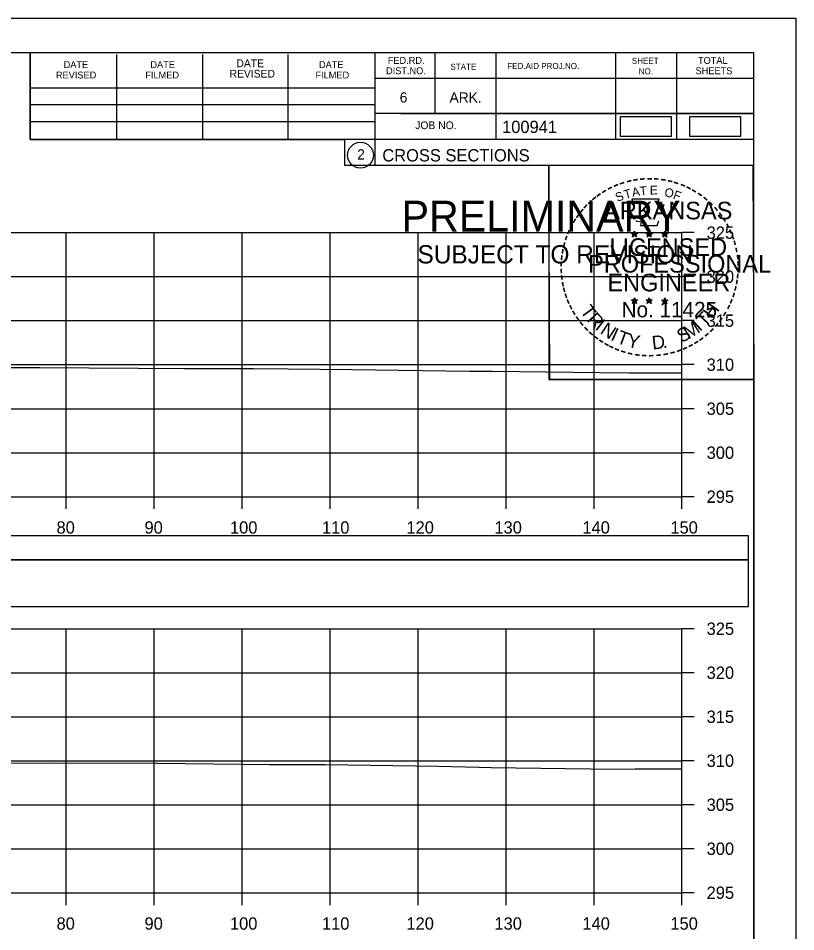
# Model space of a CAD drawing. Extents: x 1370538 to 1372872, y 376220 to 381127.
# Drawn here: x 1371449.9 to 1371538.2, y 380794.6 to 380898.4 of the extents above; entities that cross this region are included whole.
import ezdxf

# ---------------------------------------------------------------- set-up
doc = ezdxf.new("R2010")
doc.units = 0
for name, color, linetype in [('Default', 7, 'Continuous'), ('R_Border Notes', 7, 'Continuous'), ('R_Border PE', 7, 'Continuous'), ('R_Border Prem', 7, 'Continuous'), ('R_Dimension', 7, 'Continuous'), ('R_Grid', 7, 'Continuous'), ('R_No Plot', 7, 'Continuous'), ('T_Detection Zones', 7, 'Continuous'), ('T_Indications', 7, 'Continuous'), ('T_Notes', 7, 'Continuous')]:
    doc.layers.add(name, color=color, linetype=linetype)

msp = doc.modelspace()

# ---------------------------------------------------------------- linework, layer by layer
at = {"layer": 'Default'}
for points in [[(1371518.28, 380885), (1371524.11, 380885), (1371524.11, 380887.19), (1371518.28, 380887.19)], [(1371526.15, 380885), (1371531.98, 380885), (1371531.98, 380887.19), (1371526.15, 380887.19)]]:
    msp.add_lwpolyline(points, close=True, dxfattribs=at)
at = {"layer": 'R_Border Notes'}
for p, q in [((1371217.29, 380894.5), (1371533.47, 380894.5)), ((1371451.21, 380884.62), (1371451.21, 380894.5)), ((1371461.07, 380884.62), (1371461.07, 380894.3)), ((1371470.83, 380884.62), (1371470.83, 380894.3)), ((1371480.51, 380884.62), (1371480.51, 380894.3)), ((1371490.37, 380894.5), (1371490.37, 380881.7)), ((1371497.21, 380894.5), (1371497.21, 380887.56)), ((1371504.15, 380894.5), (1371504.15, 380884.62)), ((1371517.73, 380894.5), (1371517.73, 380884.62)), ((1371524.67, 380894.5), (1371524.67, 380884.62)), ((1371533.47, 380689.04), (1371533.47, 380894.5)), ((1371533.47, 380891.56), (1371490.37, 380891.56)), ((1371533.47, 380891.58), (1371533.47, 380891.58)), ((1371451.21, 380890.48), (1371490.37, 380890.48)), ((1371451.21, 380888.62), (1371490.37, 380888.62)), ((1371533.47, 380887.56), (1371490.37, 380887.56)), ((1371493.33, 380887.56), (1371533.47, 380887.56)), ((1371451.21, 380884.62), (1371451.21, 380886.68)), ((1371451.21, 380886.68), (1371490.37, 380886.68)), ((1371533.47, 380884.62), (1371451.21, 380884.62)), ((1371490.37, 380881.7), (1371533.47, 380881.7))]:
    msp.add_line(p, q, dxfattribs=at)
msp.add_circle((1371488.75, 380882.84), 1.47, dxfattribs=at)
at = {"layer": 'R_Border Prem'}
for p, q in [((1371525.29, 380844.04), (1371525.29, 380874.04)), ((1371526.69, 380874.04), (1371525.29, 380874.04)), ((1371526.69, 380869.04), (1371525.29, 380869.04)), ((1371526.69, 380864.04), (1371525.29, 380864.04)), ((1371526.69, 380859.04), (1371525.29, 380859.04)), ((1371526.69, 380854.04), (1371525.29, 380854.04)), ((1371526.69, 380849.04), (1371525.29, 380849.04)), ((1371225.29, 380844.04), (1371525.29, 380844.04)), ((1371455.29, 380842.64), (1371455.29, 380844.04)), ((1371465.29, 380842.64), (1371465.29, 380844.04)), ((1371475.29, 380842.64), (1371475.29, 380844.04)), ((1371485.29, 380842.64), (1371485.29, 380844.04)), ((1371495.29, 380842.64), (1371495.29, 380844.04)), ((1371505.29, 380842.64), (1371505.29, 380844.04)), ((1371515.29, 380842.64), (1371515.29, 380844.04)), ((1371525.29, 380842.64), (1371525.29, 380844.04)), ((1371526.69, 380844.04), (1371525.29, 380844.04)), ((1371525.29, 380799.04), (1371525.29, 380829.04)), ((1371526.69, 380829.04), (1371525.29, 380829.04)), ((1371526.69, 380824.04), (1371525.29, 380824.04)), ((1371526.69, 380819.04), (1371525.29, 380819.04)), ((1371526.69, 380814.04), (1371525.29, 380814.04)), ((1371526.69, 380809.04), (1371525.29, 380809.04)), ((1371526.69, 380804.04), (1371525.29, 380804.04)), ((1371225.29, 380799.04), (1371525.29, 380799.04)), ((1371455.29, 380797.64), (1371455.29, 380799.04)), ((1371465.29, 380797.64), (1371465.29, 380799.04)), ((1371475.29, 380797.64), (1371475.29, 380799.04)), ((1371485.29, 380797.64), (1371485.29, 380799.04)), ((1371495.29, 380797.64), (1371495.29, 380799.04)), ((1371505.29, 380797.64), (1371505.29, 380799.04)), ((1371515.29, 380797.64), (1371515.29, 380799.04)), ((1371525.29, 380797.64), (1371525.29, 380799.04)), ((1371526.69, 380799.04), (1371525.29, 380799.04))]:
    msp.add_line(p, q, dxfattribs=at)
at = {"layer": 'R_Dimension'}
for points in [[(1371401.53, 380858.5), (1371411.24, 380858.63), (1371422.37, 380858.75), (1371423.05, 380858.75), (1371427.22, 380858.76), (1371442.19, 380858.7), (1371448.25, 380858.71), (1371452.25, 380858.7), (1371463.47, 380858.64), (1371468.75, 380858.6), (1371476.59, 380858.6), (1371480.51, 380858.56), (1371487.78, 380858.49), (1371501.13, 380858.31), (1371503.75, 380858.29), (1371515.95, 380858.14), (1371519.26, 380858.1), (1371525.29, 380858.11)], [(1371402.33, 380813.37), (1371403.69, 380813.56), (1371411.36, 380813.67), (1371417.41, 380813.73), (1371422.22, 380813.78), (1371424.91, 380813.79), (1371434.55, 380813.75), (1371453.42, 380813.78), (1371465.6, 380813.75), (1371465.66, 380813.75), (1371478.42, 380813.62), (1371484.75, 380813.6), (1371497.59, 380813.41), (1371502.24, 380813.31), (1371503.61, 380813.28), (1371517.7, 380813.09), (1371519.96, 380813.11), (1371520.68, 380813.12), (1371525.29, 380813.12)]]:
    msp.add_lwpolyline(points, dxfattribs=at)
at = {"layer": 'R_Grid'}
for p, q in [((1371225.29, 380874.04), (1371525.29, 380874.04)), ((1371455.29, 380844.04), (1371455.29, 380874.04)), ((1371465.29, 380844.04), (1371465.29, 380874.04)), ((1371475.29, 380844.04), (1371475.29, 380874.04)), ((1371485.29, 380844.04), (1371485.29, 380874.04)), ((1371495.29, 380844.04), (1371495.29, 380874.04)), ((1371505.29, 380844.04), (1371505.29, 380874.04)), ((1371515.29, 380844.04), (1371515.29, 380874.04)), ((1371525.29, 380844.04), (1371525.29, 380874.04)), ((1371225.29, 380869.04), (1371525.29, 380869.04)), ((1371225.29, 380864.04), (1371525.29, 380864.04)), ((1371225.29, 380859.04), (1371525.29, 380859.04)), ((1371225.29, 380854.04), (1371525.29, 380854.04)), ((1371225.29, 380849.04), (1371525.29, 380849.04)), ((1371225.29, 380844.04), (1371525.29, 380844.04)), ((1371225.29, 380829.04), (1371525.29, 380829.04)), ((1371455.29, 380799.04), (1371455.29, 380829.04)), ((1371465.29, 380799.04), (1371465.29, 380829.04)), ((1371475.29, 380799.04), (1371475.29, 380829.04)), ((1371485.29, 380799.04), (1371485.29, 380829.04)), ((1371495.29, 380799.04), (1371495.29, 380829.04)), ((1371505.29, 380799.04), (1371505.29, 380829.04)), ((1371515.29, 380799.04), (1371515.29, 380829.04)), ((1371525.29, 380799.04), (1371525.29, 380829.04)), ((1371225.29, 380824.04), (1371525.29, 380824.04)), ((1371225.29, 380819.04), (1371525.29, 380819.04)), ((1371225.29, 380814.04), (1371525.29, 380814.04)), ((1371225.29, 380809.04), (1371525.29, 380809.04)), ((1371225.29, 380804.04), (1371525.29, 380804.04)), ((1371225.29, 380799.04), (1371525.29, 380799.04))]:
    msp.add_line(p, q, dxfattribs=at)
at = {"layer": 'R_No Plot'}
for p, q in [((1371204.89, 380898.4), (1371538.22, 380898.4)), ((1371509.5, 380859.25), (1371509.5, 380859.25))]:
    msp.add_line(p, q, dxfattribs=at)
for points in [[(1371204.88, 380898.4), (1371538.22, 380898.4), (1371538.22, 380685.06), (1371204.88, 380685.06)], [(1371451.21, 380894.5), (1371451.21, 380884.62), (1371486.94, 380884.62), (1371486.94, 380881.7), (1371510.14, 380881.7), (1371510.14, 380857.37), (1371533.47, 380857.37), (1371533.47, 380689.04), (1371217.29, 380689.04), (1371217.29, 380894.5)], [(1371510.14, 380881.7), (1371533.35, 380881.7), (1371533.47, 380857.37), (1371510.26, 380857.37)]]:
    msp.add_lwpolyline(points, close=True, dxfattribs=at)
at = {"layer": 'T_Detection Zones'}
for points in [[(1371217.73, 380836.87), (1371532.86, 380836.87), (1371532.86, 380839.58), (1371217.73, 380839.58)], [(1371217.73, 380831.55), (1371532.86, 380831.55), (1371532.86, 380836.87), (1371217.73, 380836.87)]]:
    msp.add_lwpolyline(points, close=True, dxfattribs=at)
at = {"layer": 'T_Indications'}
for p, q in [((1371519.55, 380873.96), (1371519.9, 380873.85)), ((1371519.55, 380873.96), (1371519.8, 380873.91)), ((1371519.55, 380873.96), (1371519.79, 380873.84)), ((1371519.68, 380873.55), (1371519.9, 380873.85)), ((1371519.68, 380873.55), (1371519.81, 380873.8)), ((1371519.68, 380873.55), (1371519.9, 380873.77)), ((1371519.9, 380874.21), (1371519.86, 380873.96)), ((1371519.9, 380873.85), (1371519.9, 380874.21)), ((1371519.9, 380874.21), (1371519.95, 380873.96)), ((1371520.25, 380873.96), (1371519.9, 380873.85)), ((1371520.11, 380873.55), (1371519.9, 380873.85)), ((1371520.11, 380873.55), (1371519.9, 380873.77)), ((1371520.25, 380873.96), (1371519.96, 380873.91)), ((1371520.11, 380873.55), (1371519.98, 380873.84)), ((1371520.25, 380873.96), (1371520.04, 380873.86)), ((1371521.22, 380873.96), (1371521.57, 380873.85)), ((1371521.22, 380873.96), (1371521.47, 380873.91)), ((1371521.22, 380873.96), (1371521.46, 380873.84)), ((1371521.35, 380873.55), (1371521.57, 380873.85)), ((1371521.35, 380873.55), (1371521.48, 380873.8)), ((1371521.35, 380873.55), (1371521.57, 380873.77)), ((1371521.57, 380874.21), (1371521.53, 380873.96)), ((1371521.57, 380873.85), (1371521.57, 380874.21)), ((1371521.57, 380874.21), (1371521.62, 380873.96)), ((1371521.92, 380873.96), (1371521.57, 380873.85)), ((1371521.78, 380873.55), (1371521.57, 380873.85)), ((1371521.78, 380873.55), (1371521.57, 380873.77)), ((1371521.92, 380873.96), (1371521.63, 380873.91)), ((1371521.78, 380873.55), (1371521.65, 380873.84)), ((1371521.92, 380873.96), (1371521.71, 380873.86)), ((1371522.99, 380873.95), (1371523.33, 380873.84)), ((1371522.99, 380873.95), (1371523.24, 380873.9)), ((1371522.99, 380873.95), (1371523.22, 380873.83)), ((1371523.12, 380873.54), (1371523.33, 380873.84)), ((1371523.12, 380873.54), (1371523.24, 380873.78)), ((1371523.12, 380873.54), (1371523.33, 380873.76)), ((1371523.33, 380874.2), (1371523.29, 380873.95)), ((1371523.33, 380873.84), (1371523.33, 380874.2)), ((1371523.33, 380874.2), (1371523.38, 380873.95)), ((1371523.68, 380873.95), (1371523.33, 380873.84)), ((1371523.55, 380873.54), (1371523.33, 380873.84)), ((1371523.55, 380873.54), (1371523.33, 380873.75)), ((1371523.68, 380873.95), (1371523.4, 380873.9)), ((1371523.55, 380873.54), (1371523.41, 380873.83)), ((1371523.68, 380873.95), (1371523.48, 380873.85)), ((1371519.55, 380866.39), (1371519.9, 380866.28)), ((1371519.55, 380866.39), (1371519.8, 380866.34)), ((1371519.55, 380866.39), (1371519.78, 380866.26)), ((1371519.68, 380865.98), (1371519.9, 380866.28)), ((1371519.9, 380866.64), (1371519.86, 380866.39)), ((1371519.9, 380866.28), (1371519.9, 380866.64)), ((1371519.9, 380866.64), (1371519.95, 380866.39)), ((1371520.24, 380866.39), (1371519.9, 380866.28)), ((1371520.11, 380865.98), (1371519.9, 380866.28)), ((1371520.24, 380866.39), (1371519.96, 380866.34)), ((1371520.11, 380865.98), (1371519.97, 380866.27)), ((1371520.24, 380866.39), (1371520.04, 380866.28)), ((1371521.22, 380866.39), (1371521.57, 380866.28)), ((1371521.22, 380866.39), (1371521.47, 380866.34)), ((1371521.22, 380866.39), (1371521.45, 380866.26)), ((1371521.35, 380865.98), (1371521.57, 380866.28)), ((1371521.57, 380866.64), (1371521.52, 380866.39)), ((1371521.57, 380866.28), (1371521.57, 380866.64)), ((1371521.57, 380866.64), (1371521.61, 380866.39)), ((1371521.91, 380866.39), (1371521.57, 380866.28)), ((1371521.78, 380865.98), (1371521.57, 380866.28)), ((1371521.91, 380866.39), (1371521.63, 380866.34)), ((1371521.78, 380865.98), (1371521.64, 380866.27)), ((1371521.91, 380866.39), (1371521.71, 380866.28)), ((1371522.98, 380866.38), (1371523.33, 380866.27)), ((1371522.98, 380866.38), (1371523.24, 380866.33)), ((1371522.98, 380866.38), (1371523.22, 380866.25)), ((1371523.33, 380866.63), (1371523.29, 380866.38)), ((1371523.33, 380866.27), (1371523.33, 380866.63)), ((1371523.33, 380866.63), (1371523.38, 380866.38)), ((1371523.68, 380866.38), (1371523.33, 380866.27)), ((1371523.68, 380866.38), (1371523.39, 380866.33)), ((1371523.68, 380866.38), (1371523.48, 380866.27)), ((1371519.68, 380865.98), (1371519.81, 380866.22)), ((1371519.68, 380865.98), (1371519.89, 380866.2)), ((1371520.11, 380865.98), (1371519.89, 380866.19)), ((1371521.35, 380865.98), (1371521.48, 380866.22)), ((1371521.35, 380865.98), (1371521.56, 380866.2)), ((1371521.78, 380865.98), (1371521.56, 380866.19)), ((1371523.12, 380865.97), (1371523.33, 380866.27)), ((1371523.12, 380865.97), (1371523.24, 380866.21)), ((1371523.12, 380865.97), (1371523.33, 380866.19)), ((1371523.55, 380865.97), (1371523.33, 380866.27)), ((1371523.55, 380865.97), (1371523.33, 380866.18)), ((1371523.55, 380865.97), (1371523.41, 380866.26))]:
    msp.add_line(p, q, dxfattribs=at)
for points in [[(1371519.59, 380877.84), (1371519.86, 380877.01)], [(1371523.1, 380876.92), (1371523.25, 380877.2), (1371522.56, 380877.18), (1371522.71, 380877.84), (1371519.59, 380877.84)], [(1371520.08, 380875.41), (1371520.08, 380875.33), (1371520.65, 380875.31), (1371520.59, 380874.84), (1371522.46, 380874.84), (1371522.66, 380875.37)], [(1371519.9, 380874.21), (1371520.11, 380873.55), (1371519.55, 380873.96), (1371520.25, 380873.96), (1371519.68, 380873.55), (1371519.9, 380874.21)], [(1371521.57, 380874.21), (1371521.78, 380873.55), (1371521.22, 380873.96), (1371521.92, 380873.96), (1371521.35, 380873.55), (1371521.57, 380874.21)], [(1371523.33, 380874.2), (1371523.55, 380873.54), (1371522.99, 380873.95), (1371523.68, 380873.95), (1371523.12, 380873.54), (1371523.33, 380874.2)], [(1371519.9, 380866.64), (1371520.11, 380865.98), (1371519.55, 380866.39), (1371520.24, 380866.39), (1371519.68, 380865.98), (1371519.9, 380866.64)], [(1371521.57, 380866.64), (1371521.78, 380865.98), (1371521.22, 380866.39), (1371521.91, 380866.39), (1371521.35, 380865.98), (1371521.57, 380866.64)], [(1371523.33, 380866.63), (1371523.55, 380865.97), (1371522.98, 380866.38), (1371523.68, 380866.38), (1371523.12, 380865.97), (1371523.33, 380866.63)]]:
    msp.add_lwpolyline(points, dxfattribs=at)
for centre, radius in [((1371519.9, 380873.85), 0.172), ((1371519.9, 380873.85), 0.145), ((1371519.9, 380873.85), 0.116), ((1371519.9, 380873.85), 0.0991), ((1371519.9, 380873.85), 0.0747), ((1371519.9, 380873.85), 0.0495), ((1371519.9, 380873.85), 0.0296), ((1371521.57, 380873.85), 0.172), ((1371521.57, 380873.85), 0.145), ((1371521.57, 380873.85), 0.116), ((1371521.57, 380873.85), 0.0991), ((1371521.57, 380873.85), 0.0747), ((1371521.57, 380873.85), 0.0495), ((1371521.57, 380873.85), 0.0296), ((1371523.33, 380873.84), 0.172), ((1371523.33, 380873.84), 0.145), ((1371523.33, 380873.84), 0.116), ((1371523.33, 380873.84), 0.0991), ((1371523.33, 380873.84), 0.0747), ((1371523.33, 380873.84), 0.0495), ((1371523.33, 380873.84), 0.0296), ((1371519.9, 380866.27), 0.172), ((1371519.9, 380866.27), 0.145), ((1371519.9, 380866.27), 0.116), ((1371519.9, 380866.27), 0.0991), ((1371519.9, 380866.27), 0.0747), ((1371519.9, 380866.27), 0.0495), ((1371519.9, 380866.27), 0.0296), ((1371521.56, 380866.27), 0.172), ((1371521.56, 380866.27), 0.145), ((1371521.56, 380866.27), 0.116), ((1371521.56, 380866.27), 0.0991), ((1371521.56, 380866.27), 0.0747), ((1371521.56, 380866.27), 0.0495), ((1371521.56, 380866.27), 0.0296), ((1371523.33, 380866.26), 0.172), ((1371523.33, 380866.26), 0.145), ((1371523.33, 380866.26), 0.116), ((1371523.33, 380866.26), 0.0991), ((1371523.33, 380866.26), 0.0747), ((1371523.33, 380866.26), 0.0495), ((1371523.33, 380866.26), 0.0296)]:
    msp.add_circle(centre, radius, dxfattribs=at)

# ---------------------------------------------------------------- texts
at = {"layer": 'R_Border Notes'}
for s, height, p in [('DATE', 0.782, (1371455.01, 380892.74)), ('DATE', 0.782, (1371464.87, 380892.74)), ('DATE', 0.879, (1371474.65, 380892.84)), ('DATE', 0.782, (1371484.03, 380892.74)), ('FED.RD.', 0.782, (1371491.85, 380893.22)), ('FED.AID PROJ.NO.', 0.684, (1371505.43, 380892.64)), ('SHEET', 0.684, (1371519.59, 380893.22)), ('TOTAL', 0.782, (1371527.11, 380893.22)), ('REVISED', 0.782, (1371454.13, 380891.56)), ('FILMED', 0.782, (1371464.29, 380891.56)), ('REVISED', 0.879, (1371473.87, 380891.66)), ('FILMED', 0.782, (1371483.63, 380891.56)), ('DIST.NO.', 0.782, (1371491.65, 380892.04)), ('STATE', 0.684, (1371498.97, 380892.54)), ('NO.', 0.684, (1371520.37, 380892.04)), ('SHEETS', 0.782, (1371526.83, 380892.04)), ('6', 1.17, (1371493.21, 380888.82)), ('ARK.', 1.172, (1371498.87, 380888.82)), ('JOB NO.', 0.879, (1371494.97, 380885.8)), ('100941', 1.4, (1371504.84, 380885.36)), ('2', 1.17, (1371488.37, 380882.35)), ('CROSS SECTIONS', 1.4, (1371491.23, 380882.13))]:
    msp.add_text(s, height=height, rotation=360, dxfattribs=at).set_placement(p)
at = {"layer": 'R_Border PE'}
for s, p in [('325', (1371528.09, 380873.34)), ('320', (1371528.09, 380868.34)), ('315', (1371528.09, 380863.34)), ('310', (1371528.09, 380858.34)), ('305', (1371528.09, 380853.34)), ('300', (1371528.09, 380848.34)), ('295', (1371528.09, 380843.34)), ('80', (1371454.2, 380839.84)), ('90', (1371464.2, 380839.84)), ('100', (1371473.91, 380839.84)), ('110', (1371484.37, 380839.84)), ('120', (1371493.97, 380839.84)), ('130', (1371503.97, 380839.84)), ('140', (1371513.97, 380839.84)), ('150', (1371523.97, 380839.84)), ('325', (1371528.09, 380828.34)), ('320', (1371528.09, 380823.34)), ('315', (1371528.09, 380818.34)), ('310', (1371528.09, 380813.34)), ('305', (1371528.09, 380808.34)), ('300', (1371528.09, 380803.34)), ('295', (1371528.09, 380798.34)), ('80', (1371454.2, 380794.84)), ('90', (1371464.2, 380794.84)), ('100', (1371473.91, 380794.84)), ('110', (1371484.37, 380794.84)), ('120', (1371493.97, 380794.84)), ('130', (1371503.97, 380794.84)), ('140', (1371513.97, 380794.84)), ('150', (1371523.97, 380794.84))]:
    msp.add_text(s, height=1.4, dxfattribs=at).set_placement(p)
at = {"layer": 'T_Indications'}
for s, height, rotation, p in [('-', 1.6, 19.1761, (1371518.34, 380878.96)), ('-', 1.6, 13.6301, (1371519.09, 380879.21)), ('-', 1.6, 10.2193, (1371519.77, 380879.37)), ('-', 1.6, 5.8968, (1371520.5, 380879.48)), ('-', 1.6, 0.1862, (1371521.27, 380879.55)), ('-', 1.6, 357.743, (1371521.99, 380879.54)), ('-', 1.6, 352.1617, (1371522.74, 380879.48)), ('-', 1.6, 347.2049, (1371523.46, 380879.37)), ('-', 1.6, 342.3362, (1371524.09, 380879.21)), ('-', 1.6, 34.0636, (1371516.48, 380878.01)), ('-', 1.6, 28.7918, (1371517.07, 380878.38)), ('-', 1.6, 24.3072, (1371517.71, 380878.7)), ('T', 1, 16.4036, (1371518.86, 380877.85)), ('A', 1, 11.2132, (1371519.69, 380878.1)), ('T', 1, 6.0228, (1371520.54, 380878.26)), ('E', 1, 0.8323, (1371521.64, 380878.37)), ('O', 1, 350.4515, (1371523.25, 380878.16)), ('F', 1, 340.0707, (1371524.2, 380877.94)), ('-', 1.6, 337.8551, (1371524.83, 380878.99)), ('-', 1.6, 334.1211, (1371525.46, 380878.72)), ('-', 1.6, 329.6409, (1371526.04, 380878.43)), ('-', 1.6, 42.9622, (1371514.99, 380876.82)), ('-', 1.6, 38.9507, (1371515.42, 380877.24)), ('-', 1.6, 36.2317, (1371515.9, 380877.61)), ('S', 1, 21.594, (1371517.95, 380877.52)), ('-', 1.6, 325.8627, (1371526.68, 380878.07)), ('-', 1.6, 320.5297, (1371527.29, 380877.65)), ('-', 1.6, 50.6142, (1371514.14, 380875.85)), ('-', 1.6, 48.423, (1371514.54, 380876.34)), ('ARKANSAS', 2, 360, (1371516.45, 380875.55)), ('-', 1.6, 315.5786, (1371527.89, 380877.16)), ('-', 1.6, 309.8797, (1371528.46, 380876.61)), ('-', 1.6, 58.0706, (1371513.4, 380874.76)), ('-', 1.6, 54.2325, (1371513.73, 380875.29)), ('-', 1.6, 306.6522, (1371528.98, 380876.01)), ('-', 1.4, 303.6753, (1371529.47, 380875.44)), ('-', 1.6, 62.8713, (1371513.09, 380874.15)), ('-', 1.6, 299.6684, (1371529.79, 380874.83)), ('-', 1.6, 72.3945, (1371512.61, 380872.91)), ('-', 1.6, 67.7743, (1371512.83, 380873.54)), ('DWB', 0.01, 360, (1371519.89, 380873.84)), ('DWB', 0.01, 360, (1371521.56, 380873.84)), ('DWB', 0.01, 360, (1371523.32, 380873.83)), ('-', 1.6, 294.6628, (1371530.11, 380874.22)), ('-', 1.6, 290.5728, (1371530.37, 380873.64)), ('-', 1.6, 75.461, (1371512.41, 380872.19)), ('LICENSED', 2, 360, (1371517.04, 380871.4)), ('-', 1.6, 285.1233, (1371530.6, 380873.06)), ('-', 1.6, 85.1863, (1371512.2, 380870.79)), ('-', 1.6, 81.2013, (1371512.28, 380871.48)), ('PROFESSIONAL', 2, 360, (1371514.62, 380869.5)), ('-', 1.6, 280.5493, (1371530.8, 380872.32)), ('-', 1.6, 276.5962, (1371530.96, 380871.55)), ('-', 1.6, 89.0622, (1371512.18, 380870.09)), ('-', 1.6, 274.3301, (1371531.02, 380870.83)), ('-', 1.6, 94.1959, (1371512.21, 380869.36)), ('ENGINEER', 2, 360, (1371516.81, 380867.37)), ('-', 1.6, 269.9407, (1371531.06, 380870.2)), ('-', 1.6, 98.9479, (1371512.29, 380868.69)), ('-', 1.6, 101.7149, (1371512.42, 380867.96)), ('-', 1.6, 260.9953, (1371530.97, 380868.88)), ('-', 1.6, 263.5172, (1371531.04, 380869.53)), ('-', 1.6, 105.4578, (1371512.58, 380867.37)), ('-', 1.6, 255.7626, (1371530.86, 380868.2)), ('-', 1.6, 109.0874, (1371512.8, 380866.74)), ('-', 1.6, 114.0643, (1371513.05, 380866.14)), ('DWB', 0.01, 360, (1371519.88, 380866.27)), ('DWB', 0.01, 360, (1371521.55, 380866.27)), ('DWB', 0.01, 360, (1371523.32, 380866.26)), ('-', 1.6, 247.8887, (1371530.45, 380866.81)), ('-', 1.6, 252.8681, (1371530.68, 380867.48)), ('-', 1.6, 115.7289, (1371513.36, 380865.52)), ('T', 1.54, 306.0406, (1371513.66, 380865.11)), ('No. 11425', 1.757, 360, (1371518.43, 380864.42)), ('H', 1.54, 54.6088, (1371528.78, 380864.15)), ('-', 1.6, 244.6197, (1371530.19, 380866.18)), ('-', 1.6, 120.4471, (1371513.71, 380864.94)), ('-', 1.6, 125.8934, (1371514.12, 380864.37)), ('R', 1.54, 314.005, (1371514.42, 380864.07)), ('I', 1.54, 321.9694, (1371515.32, 380863.13)), ('T', 1.54, 46.6444, (1371527.89, 380863.21)), ('-', 1.6, 233.8452, (1371529.4, 380864.77)), ('-', 1.6, 239.0712, (1371529.8, 380865.43)), ('-', 1.6, 130.7181, (1371514.58, 380863.82)), ('-', 1.6, 134.2238, (1371515.1, 380863.28)), ('N', 1.54, 326.5002, (1371515.89, 380862.66)), ('I', 1.54, 335.3603, (1371517.09, 380861.88)), ('S', 1.54, 26.9312, (1371525.2, 380861.48)), ('M', 1.54, 32.6563, (1371526.04, 380861.88)), ('I', 1.54, 42.1136, (1371527.32, 380862.73)), ('-', 1.6, 225.7653, (1371528.49, 380863.64)), ('-', 1.6, 231.2538, (1371528.97, 380864.21)), ('-', 1.6, 138.9338, (1371515.62, 380862.81)), ('-', 1.6, 144.6463, (1371516.18, 380862.41)), ('T', 1.54, 339.8912, (1371517.76, 380861.55)), ('Y', 1.54, 347.8556, (1371518.97, 380861.1)), ('D', 1.54, 6.3969, (1371521.96, 380860.75)), ('-', 1.6, 215.7363, (1371527.42, 380862.66)), ('-', 1.6, 221.0851, (1371527.96, 380863.14)), ('-', 1.6, 148.0898, (1371516.74, 380862.04)), ('-', 1.6, 151.5704, (1371517.32, 380861.71)), ('-', 1.6, 154.6002, (1371517.84, 380861.46)), ('.', 1.54, 13.7642, (1371523.15, 380860.87)), ('-', 1.6, 204.2516, (1371525.7, 380861.61)), ('-', 1.6, 207.3568, (1371526.32, 380861.93)), ('-', 1.6, 212.2491, (1371526.88, 380862.28)), ('-', 1.6, 158.5612, (1371518.46, 380861.21)), ('-', 1.6, 162.7983, (1371519.15, 380861)), ('-', 1.6, 167.5555, (1371519.87, 380860.83)), ('-', 1.6, 173.1155, (1371520.64, 380860.72)), ('-', 1.6, 176.5183, (1371521.39, 380860.67)), ('-', 1.6, 181.5918, (1371522.13, 380860.69)), ('-', 1.6, 185.8167, (1371522.94, 380860.77)), ('-', 1.6, 191.2858, (1371523.67, 380860.9)), ('-', 1.6, 195.4743, (1371524.4, 380861.1)), ('-', 1.6, 200.7184, (1371525.08, 380861.34))]:
    msp.add_text(s, height=height, rotation=rotation, dxfattribs=at).set_placement(p)
at = {"layer": 'T_Notes'}
for s, height, p in [('PRELIMINARY', 3.5, (1371493.42, 380874.17)), ('DWB', 0.01, (1371494.16, 380876.02)), ('SUBJECT TO REVISION', 2.0751, (1371495.23, 380870.54))]:
    msp.add_text(s, height=height, rotation=360, dxfattribs=at).set_placement(p)

doc.saveas('drawing.dxf')
